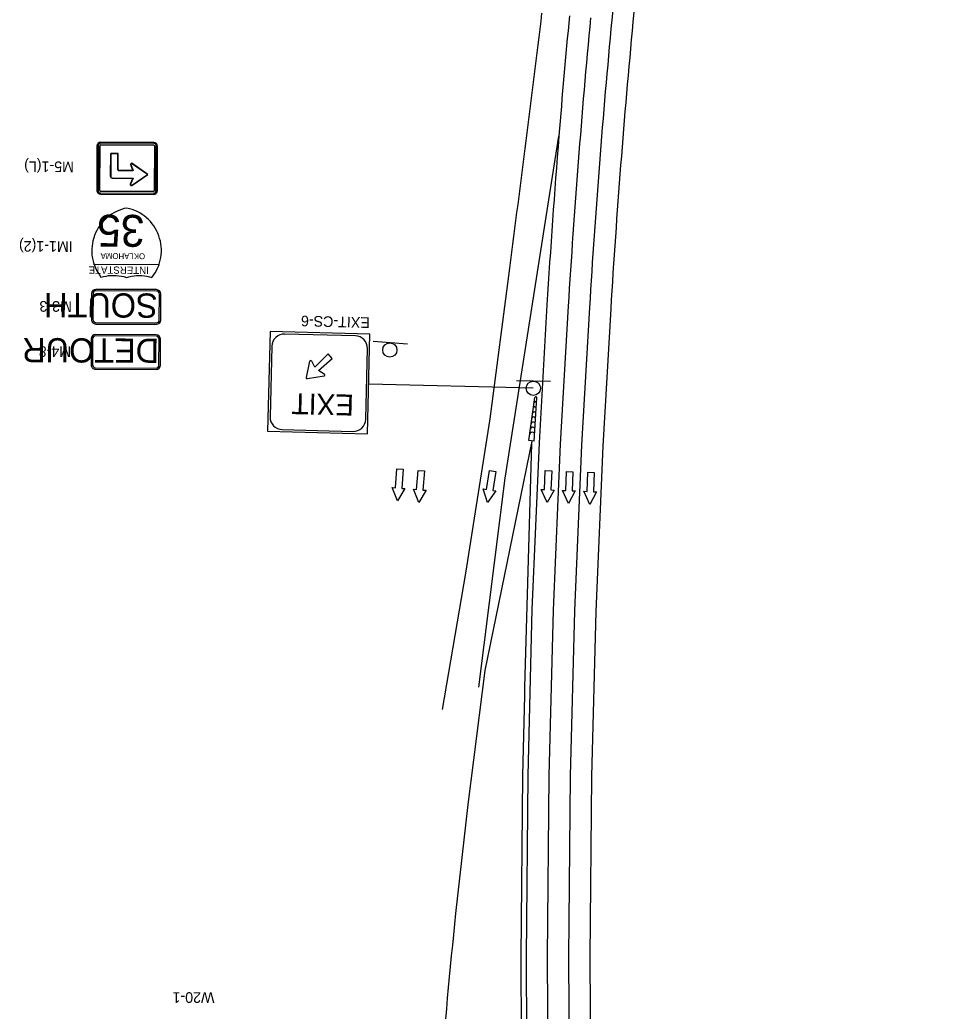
# Model space of a CAD drawing. Extents: x 2135767 to 2151731, y 141839 to 175894.
# Drawn here: x 2150479 to 2151007, y 146342 to 146901 of the extents above; entities that cross this region are included whole.
import ezdxf

# ---------------------------------------------------------------- set-up
doc = ezdxf.new("R2010")
doc.units = 0
for name, color, linetype in [('Default', 7, 'Continuous'), ('PR_Dimensions_Phase1', 7, 'Continuous'), ('PR_Phasing_Detour_1', 7, 'Continuous'), ('PR_Phasing_Traffic_Barrier_Phase_1', 7, 'Continuous'), ('PR_Phasing_Traffic_Control_Devices_1', 7, 'Continuous'), ('PR_Phasing_Traffic_Striping_Dashed_Phase_1', 7, 'Continuous'), ('PR_Phasing_Traffic_Striping_White_Phase_1', 7, 'Continuous'), ('PR_Phasing_Traffic_Striping_Yellow_Phase_1', 7, 'Continuous'), ('Pr_Traffic_Arrows_Phase_1', 7, 'Continuous'), ('PR_Traffic_Striping_Dashed', 7, 'Continuous'), ('PR_Txt_Phase_1', 7, 'Continuous')]:
    doc.layers.add(name, color=color, linetype=linetype)

# ---------------------------------------------------------------- blocks, each defined once
blk = doc.blocks.new('GRTATT')
at = {"layer": 'Default'}
for p, q in [((-0.09, 1.53), (-24.49, -0.82)), ((-0.03, 1.54), (0.03, -1.54)), ((0.09, -1.53), (-24.44, -1.81))]:
    blk.add_line(p, q, dxfattribs=at)
for centre, radius in [((-15.48, -0.83), 0.878), ((-12.48, -0.67), 1.01), ((-9.49, -0.51), 1.13), ((-6.49, -0.35), 1.26), ((-3.49, -0.19), 1.39), ((-24.46, -1.32), 0.496), ((-21.47, -1.16), 0.623), ((-18.47, -1), 0.751)]:
    blk.add_arc(centre, radius, 93.1763, 273.1763, dxfattribs=at)

msp = doc.modelspace()

# ---------------------------------------------------------------- linework, layer by layer
at = {"layer": 'PR_Dimensions_Phase1'}
msp.add_line((2150768.49, 146693.37), (2150675.68, 146695.77), dxfattribs=at)
at = {"layer": 'PR_Phasing_Detour_1'}
for p, q in [((2150554.54, 146831.98), (2150524.68, 146832.14)), ((2150522.51, 146829.99), (2150522.38, 146805.01)), ((2150523.12, 146829.98), (2150522.99, 146805.01)), ((2150523.12, 146829.98), (2150522.99, 146805.01)), ((2150524.13, 146829.98), (2150524, 146805)), ((2150524, 146805), (2150524.13, 146829.98)), ((2150554.53, 146830.36), (2150524.67, 146830.51)), ((2150524.67, 146830.51), (2150554.53, 146830.36)), ((2150554.54, 146831.37), (2150524.68, 146831.53)), ((2150554.54, 146831.37), (2150524.68, 146831.53)), ((2150554.94, 146804.84), (2150555.07, 146829.82)), ((2150555.07, 146829.82), (2150554.94, 146804.84)), ((2150555.95, 146804.84), (2150556.08, 146829.81)), ((2150555.95, 146804.84), (2150556.08, 146829.81)), ((2150556.56, 146804.83), (2150556.69, 146829.81)), ((2150530.35, 146825.63), (2150530.28, 146812.99)), ((2150534.51, 146825.61), (2150530.35, 146825.63)), ((2150534.46, 146816.78), (2150534.51, 146825.61)), ((2150542.93, 146816.04), (2150535.15, 146816.08)), ((2150541.56, 146819.52), (2150542.93, 146816.04)), ((2150551.24, 146813.92), (2150542.25, 146820.21)), ((2150531.32, 146811.94), (2150542.9, 146811.88)), ((2150542.9, 146811.88), (2150541.5, 146808.42)), ((2150542.19, 146807.72), (2150551.24, 146813.92)), ((2150524.54, 146804.46), (2150554.4, 146804.31)), ((2150554.4, 146804.31), (2150524.54, 146804.46)), ((2150524.53, 146803.45), (2150554.39, 146803.29)), ((2150524.53, 146803.45), (2150554.39, 146803.29)), ((2150524.53, 146802.84), (2150554.39, 146802.68)), ((2150557.76, 146762.87), (2150520.57, 146763.06)), ((2150556.13, 146748.95), (2150521.94, 146749.13)), ((2150556.12, 146748.14), (2150521.94, 146748.32)), ((2150519.48, 146746.7), (2150519.41, 146732.05)), ((2150520.3, 146746.7), (2150520.22, 146732.04)), ((2150557.67, 146731.85), (2150557.74, 146746.5)), ((2150558.48, 146731.84), (2150558.56, 146746.5)), ((2150521.84, 146730.41), (2150556.03, 146730.23)), ((2150521.84, 146729.59), (2150556.03, 146729.42)), ((2150519.28, 146721.24), (2150519.2, 146706.59)), ((2150520.09, 146721.24), (2150520.02, 146706.59)), ((2150555.92, 146723.5), (2150521.73, 146723.67)), ((2150555.92, 146722.68), (2150521.73, 146722.86)), ((2150557.46, 146706.39), (2150557.54, 146721.05)), ((2150558.27, 146706.39), (2150558.35, 146721.04)), ((2150687.92, 146718.92), (2150678.3, 146719.67)), ((2150697.54, 146718.18), (2150687.92, 146718.92)), ((2150521.63, 146704.14), (2150555.82, 146703.96)), ((2150521.64, 146704.95), (2150555.82, 146704.77))]:
    msp.add_line(p, q, dxfattribs=at)
for points in [[(2150534.24, 146816.69), (2150534.28, 146825.51), (2150530.12, 146825.54), (2150530.05, 146812.89)], [(2150541.33, 146819.43), (2150542.7, 146815.95), (2150534.93, 146815.99)], [(2150551.01, 146813.83), (2150542.02, 146820.12)], [(2150531.09, 146811.85), (2150542.68, 146811.79), (2150541.27, 146808.33)], [(2150541.96, 146807.63), (2150551.01, 146813.83)], [(2150553.5, 146755.82), (2150554.43, 146757.07), (2150555.28, 146758.37), (2150556.04, 146759.73), (2150556.72, 146761.13), (2150557.31, 146762.57), (2150557.8, 146764.05), (2150558.2, 146765.55), (2150558.5, 146767.08), (2150558.71, 146768.62), (2150558.81, 146770.18), (2150558.82, 146771.73), (2150558.73, 146773.29), (2150558.53, 146774.83), (2150558.24, 146776.36), (2150557.86, 146777.87), (2150557.37, 146779.35), (2150556.8, 146780.8), (2150556.13, 146782.21), (2150555.38, 146783.57), (2150554.54, 146784.88), (2150553.61, 146786.13), (2150552.61, 146787.33), (2150551.54, 146788.45), (2150550.4, 146789.51), (2150549.19, 146790.49), (2150547.92, 146791.39), (2150546.59, 146792.21), (2150545.22, 146792.95), (2150543.8, 146793.59), (2150542.35, 146794.14), (2150540.86, 146794.6), (2150539.35, 146794.97), (2150537.83, 146794.62), (2150536.34, 146794.18), (2150534.87, 146793.64), (2150533.45, 146793.01), (2150532.07, 146792.29), (2150530.74, 146791.48), (2150529.46, 146790.59), (2150528.24, 146789.63), (2150527.08, 146788.58), (2150526, 146787.46), (2150524.99, 146786.28), (2150524.05, 146785.04), (2150523.2, 146783.74), (2150522.43, 146782.38), (2150521.75, 146780.98), (2150521.16, 146779.54), (2150520.66, 146778.07), (2150520.26, 146776.56), (2150519.95, 146775.03), (2150519.74, 146773.49), (2150519.63, 146771.94), (2150519.62, 146770.38), (2150519.71, 146768.83), (2150519.9, 146767.28), (2150520.19, 146765.75), (2150520.57, 146764.24), (2150521.05, 146762.76), (2150521.62, 146761.31), (2150522.28, 146759.9), (2150523.03, 146758.54), (2150523.87, 146757.23), (2150524.79, 146755.97), (2150526.19, 146756.35), (2150527.62, 146756.64), (2150529.06, 146756.85), (2150530.51, 146756.97), (2150531.97, 146757.01), (2150533.43, 146756.96), (2150534.88, 146756.82), (2150536.32, 146756.6), (2150537.74, 146756.29), (2150539.14, 146755.89), (2150540.55, 146756.27), (2150541.98, 146756.57), (2150543.42, 146756.78), (2150544.87, 146756.9), (2150546.32, 146756.94), (2150547.78, 146756.88), (2150549.23, 146756.75), (2150550.67, 146756.52), (2150552.09, 146756.21), (2150553.5, 146755.82)]]:
    msp.add_lwpolyline(points, dxfattribs=at)
msp.add_circle((2150687.61, 146714.93), 4, dxfattribs=at)
for centre, radius, start, end in [((2150524.67, 146829.98), 2.16, 89.7019, 179.7019), ((2150554.53, 146829.82), 2.16, 359.7019, 89.7019), ((2150524.67, 146829.98), 1.55, 89.7019, 179.7019), ((2150524.67, 146829.98), 1.55, 89.7019, 179.7019), ((2150524.67, 146829.98), 0.537, 89.7019, 179.7019), ((2150524.67, 146829.98), 0.537, 89.7019, 179.7019), ((2150554.53, 146829.82), 0.537, 359.7019, 89.7019), ((2150554.53, 146829.82), 0.537, 359.7019, 89.7019), ((2150554.53, 146829.82), 1.55, 359.7019, 89.7019), ((2150554.53, 146829.82), 1.55, 359.7019, 89.7019), ((2150534.93, 146816.68), 0.694, 179.7019, 269.7019), ((2150535.16, 146816.78), 0.694, 179.7019, 269.7019), ((2150542.02, 146819.42), 0.694, 89.7019, 179.7019), ((2150542.25, 146819.51), 0.694, 89.7019, 179.7019), ((2150531.09, 146812.89), 1.04, 179.7019, 269.7019), ((2150531.32, 146812.98), 1.04, 179.7019, 269.7019), ((2150524.54, 146805), 2.16, 179.7019, 269.7019), ((2150524.54, 146805), 1.55, 179.7019, 269.7019), ((2150524.54, 146805), 1.55, 179.7019, 269.7019), ((2150524.54, 146805), 0.537, 179.7019, 269.7019), ((2150524.54, 146805), 0.537, 179.7019, 269.7019), ((2150541.96, 146808.32), 0.694, 179.7019, 269.7019), ((2150542.19, 146808.42), 0.694, 179.7019, 269.7019), ((2150554.4, 146804.84), 1.55, 269.7019, 359.7019), ((2150554.4, 146804.84), 1.55, 269.7019, 359.7019), ((2150554.4, 146804.84), 2.16, 269.7019, 359.7019), ((2150554.4, 146804.84), 0.537, 269.7019, 359.7019), ((2150554.4, 146804.84), 0.537, 269.7019, 359.7019), ((2150521.93, 146746.69), 2.44, 89.7019, 179.7019), ((2150521.93, 146746.69), 1.63, 89.7019, 179.7019), ((2150556.11, 146746.51), 1.63, 359.7019, 89.7019), ((2150556.11, 146746.51), 2.44, 359.7019, 89.7019), ((2150521.85, 146732.04), 2.44, 179.7019, 269.7019), ((2150521.85, 146732.04), 1.63, 179.7019, 269.7019), ((2150556.04, 146731.86), 1.63, 269.7019, 359.7019), ((2150556.04, 146731.86), 2.44, 269.7019, 359.7019), ((2150521.72, 146721.23), 2.44, 89.7019, 179.7019), ((2150521.72, 146721.23), 1.63, 89.7019, 179.7019), ((2150555.91, 146721.05), 2.44, 359.7019, 89.7019), ((2150555.91, 146721.05), 1.63, 359.7019, 89.7019), ((2150521.64, 146706.58), 2.44, 179.7019, 269.7019), ((2150521.64, 146706.58), 1.63, 179.7019, 269.7019), ((2150555.83, 146706.4), 2.44, 269.7019, 359.7019), ((2150555.83, 146706.4), 1.63, 269.7019, 359.7019)]:
    msp.add_arc(centre, radius, start, end, dxfattribs=at)
at = {"layer": 'PR_Phasing_Traffic_Barrier_Phase_1'}
for points in [[(2150767.73, 146663.55), (2150741.1, 146534.3), (2150731.5, 146458.73), (2150724.67, 146397.25)], [(2150767.45, 146662.17), (2150763.61, 146524.79), (2150763.49, 146520.33), (2150762.33, 146475.14), (2150761.37, 146372.8), (2150761.84, 146282.68), (2150762.58, 146173.1), (2150762.81, 146051.01), (2150763.85, 145920.4), (2150764.43, 145822.04), (2150764.95, 145730.37), (2150765.18, 145690.17)]]:
    msp.add_lwpolyline(points, dxfattribs=at)
msp.add_arc((2154239.46, 146028.83), 3534.05, 174.01627, 175.56826, dxfattribs=at)
at = {"layer": 'PR_Phasing_Traffic_Control_Devices_1'}
for p, q in [((2150620.18, 146725.33), (2150618.73, 146669.1)), ((2150676.41, 146723.88), (2150620.18, 146725.33)), ((2150674.96, 146667.65), (2150676.41, 146723.88)), ((2150652.86, 146712.76), (2150645.41, 146705.35)), ((2150647.39, 146703.33), (2150655.09, 146710.23)), ((2150655.09, 146710.23), (2150652.86, 146712.76)), ((2150642.4, 146708.64), (2150640.45, 146699.44)), ((2150645.41, 146705.35), (2150643.58, 146708.58)), ((2150650.64, 146701.27), (2150647.39, 146703.33)), ((2150641.21, 146698.83), (2150650.53, 146700.3)), ((2150768.59, 146697.37), (2150758.95, 146697.62)), ((2150778.24, 146697.12), (2150768.59, 146697.37)), ((2150618.73, 146669.1), (2150674.96, 146667.65))]:
    msp.add_line(p, q, dxfattribs=at)
for points in [[(2150668.18, 146722.92), (2150628.35, 146723.95)], [(2150621.14, 146717.1), (2150620.11, 146677.27)], [(2150674, 146675.88), (2150675.03, 146715.71)], [(2150652.86, 146712.76), (2150645.41, 146705.35), (2150643.58, 146708.58)], [(2150650.64, 146701.27), (2150647.39, 146703.33), (2150655.09, 146710.23), (2150652.86, 146712.76)], [(2150642.4, 146708.64), (2150640.45, 146699.44)], [(2150641.21, 146698.83), (2150650.53, 146700.3)], [(2150626.96, 146670.06), (2150666.79, 146669.03)]]:
    msp.add_lwpolyline(points, dxfattribs=at)
msp.add_circle((2150768.49, 146693.37), 4, dxfattribs=at)
for centre, radius, start, end in [((2150628.17, 146716.92), 7.03, 88.5212, 178.5212), ((2150668, 146715.89), 7.03, 358.5212, 88.5212), ((2150642.97, 146708.24), 0.699, 29.5789, 144.6011), ((2150642.97, 146708.24), 0.699, 29.5789, 144.6011), ((2150640.99, 146699.33), 0.543, 168.0494, 293.8906), ((2150640.99, 146699.33), 0.543, 168.0494, 293.8906), ((2150650.45, 146700.8), 0.507, 278.9476, 67.6995), ((2150650.45, 146700.8), 0.507, 278.9476, 67.6995), ((2150627.14, 146677.09), 7.03, 178.5212, 268.5212), ((2150666.97, 146676.06), 7.03, 268.5212, 358.5212)]:
    msp.add_arc(centre, radius, start, end, dxfattribs=at)
at = {"layer": 'PR_Phasing_Traffic_Striping_Dashed_Phase_1'}
for points in [[(2151007.42, 147966.34), (2150962.05, 147774.13), (2150952.59, 147736.16), (2150943.64, 147699.36), (2150930.36, 147641.44), (2150923.38, 147610.45), (2150917.1, 147581.15), (2150898.5, 147491.88), (2150876.21, 147370.91), (2150860.38, 147277.43), (2150847.06, 147191.86), (2150835.17, 147103.34), (2150823.22, 147005.9), (2150812.72, 146901.05)], [(2150788.16, 146739.66), (2150783.69, 146661.92), (2150779.71, 146568.33), (2150777.32, 146474.88), (2150776.37, 146372.77), (2150776.84, 146282.77), (2150777.58, 146173.16), (2150777.81, 146051.08), (2150778.85, 145920.51), (2150779.43, 145822.12), (2150779.95, 145730.45), (2150780.18, 145690.3)], [(2150800.14, 146738.93), (2150795.68, 146661.32), (2150791.7, 146567.92), (2150789.32, 146474.67), (2150788.37, 146372.74), (2150788.84, 146282.84), (2150789.58, 146173.21), (2150789.81, 146051.14), (2150790.85, 145920.59), (2150791.43, 145822.19), (2150791.95, 145730.52), (2150792.18, 145690.37)]]:
    msp.add_lwpolyline(points, dxfattribs=at)
for radius in [4837.59, 4825.59]:
    msp.add_arc((2155616.86, 146446.48), radius, 174.59467, 176.52543, dxfattribs=at)
at = {"layer": 'PR_Phasing_Traffic_Striping_White_Phase_1'}
for points in [[(2150737.86, 146524.84), (2150752.56, 146642.63), (2150782.89, 146835.51)], [(2150717.21, 146512.25), (2150730.41, 146589.21), (2150744.09, 146676.05), (2150755.22, 146761.02)], [(2150776.18, 146740.39), (2150771.71, 146662.52), (2150767.71, 146568.74), (2150765.33, 146475.09), (2150764.37, 146372.79), (2150764.84, 146282.7), (2150765.58, 146173.11), (2150765.81, 146051.02), (2150766.85, 145920.42), (2150767.43, 145822.06), (2150767.95, 145730.38), (2150768.18, 145690.22)]]:
    msp.add_lwpolyline(points, dxfattribs=at)
for centre, radius, start, end in [((2130411.85, 149402.07), 20514.09, 352.603044, 353.00792), ((2155616.86, 146446.48), 4849.59, 175.39884, 176.52543)]:
    msp.add_arc(centre, radius, start, end, dxfattribs=at)
at = {"layer": 'PR_Phasing_Traffic_Striping_Yellow_Phase_1'}
for points in [[(2150973.73, 147771.38), (2150971.08, 147760.75), (2150964.25, 147733.29), (2150955.32, 147696.6), (2150942.06, 147638.78), (2150935.1, 147607.87), (2150928.84, 147578.67), (2150910.27, 147489.57), (2150888.03, 147368.82), (2150872.23, 147275.51), (2150858.93, 147190.14), (2150847.07, 147101.81), (2150835.15, 147004.57), (2150824.67, 146899.92)], [(2150812.11, 146738.2), (2150807.66, 146660.73), (2150803.69, 146567.51), (2150801.32, 146474.47), (2150800.37, 146372.72), (2150800.84, 146282.91), (2150801.58, 146173.27), (2150801.81, 146051.2), (2150802.85, 145920.67), (2150803.43, 145822.26), (2150803.95, 145730.59), (2150804.18, 145690.43)]]:
    msp.add_lwpolyline(points, dxfattribs=at)
msp.add_arc((2155616.86, 146446.48), 4813.59, 174.59467, 176.52543, dxfattribs=at)
at = {"layer": 'Pr_Traffic_Arrows_Phase_1'}
for p, q in [((2150690.73, 146637.2), (2150691.57, 146647.97)), ((2150691.57, 146647.97), (2150695.16, 146647.69)), ((2150695.16, 146647.69), (2150694.32, 146636.93)), ((2150702.7, 146636.28), (2150703.53, 146647.04)), ((2150703.53, 146647.04), (2150707.12, 146646.76)), ((2150707.12, 146646.76), (2150706.29, 146636)), ((2150742.08, 146636.34), (2150743.76, 146647.01)), ((2150743.76, 146647.01), (2150747.32, 146646.45)), ((2150747.32, 146646.45), (2150745.64, 146635.78)), ((2150774.79, 146636.22), (2150775.25, 146647.01)), ((2150775.25, 146647.01), (2150778.85, 146646.85)), ((2150778.85, 146646.85), (2150778.39, 146636.06)), ((2150786.78, 146635.71), (2150787.24, 146646.5)), ((2150787.24, 146646.5), (2150790.84, 146646.34)), ((2150790.84, 146646.34), (2150790.38, 146635.55)), ((2150798.77, 146635.2), (2150799.23, 146645.99)), ((2150799.23, 146645.99), (2150802.83, 146645.83)), ((2150802.83, 146645.83), (2150802.37, 146635.04)), ((2150691.97, 146629.89), (2150688.94, 146637.34)), ((2150688.94, 146637.34), (2150690.73, 146637.2)), ((2150696.12, 146636.79), (2150691.97, 146629.89)), ((2150694.32, 146636.93), (2150696.12, 146636.79)), ((2150703.93, 146628.96), (2150700.9, 146636.42)), ((2150700.9, 146636.42), (2150702.7, 146636.28)), ((2150742.74, 146628.95), (2150740.31, 146636.62)), ((2150740.31, 146636.62), (2150742.08, 146636.34)), ((2150776.28, 146628.95), (2150772.99, 146636.29)), ((2150772.99, 146636.29), (2150774.79, 146636.22)), ((2150708.08, 146635.86), (2150703.93, 146628.96)), ((2150706.29, 146636), (2150708.08, 146635.86)), ((2150747.42, 146635.5), (2150742.74, 146628.95)), ((2150745.64, 146635.78), (2150747.42, 146635.5)), ((2150780.19, 146635.99), (2150776.28, 146628.95)), ((2150778.39, 146636.06), (2150780.19, 146635.99)), ((2150788.27, 146628.44), (2150784.98, 146635.78)), ((2150784.98, 146635.78), (2150786.78, 146635.71)), ((2150792.17, 146635.48), (2150788.27, 146628.44)), ((2150790.38, 146635.55), (2150792.17, 146635.48)), ((2150800.26, 146627.93), (2150796.97, 146635.27)), ((2150796.97, 146635.27), (2150798.77, 146635.2)), ((2150804.16, 146634.97), (2150800.26, 146627.93)), ((2150802.37, 146635.04), (2150804.16, 146634.97))]:
    msp.add_line(p, q, dxfattribs=at)
at = {"layer": 'PR_Traffic_Striping_Dashed'}
msp.add_arc((2155616.86, 146446.48), 4849.59, 174.59467, 175.39884, dxfattribs=at)

# ---------------------------------------------------------------- block references
at = {"layer": 'PR_Phasing_Traffic_Control_Devices_1', "rotation": -98.69831043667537}
msp.add_blockref('GRTATT', (2150767.49, 146663.74), dxfattribs=at)

# ---------------------------------------------------------------- texts
at = {"layer": 'PR_Phasing_Detour_1'}
for s, height, p in [('M5-1(L)', 6, (2150509.56, 146821.16)), ('35', 17.974, (2150549.37, 146791.07)), ('IM1-1(2)', 6, (2150508.87, 146776.23)), ('OKLAHOMA', 3.31, (2150549.67, 146769.44)), ('INTERSTATE', 4.084, (2150551.8, 146761.9)), ('M3-3', 6, (2150508.38, 146742.43)), ('SOUTH', 13.675, (2150556.75, 146746.78)), ('DETOUR', 13.675, (2150557.59, 146721.32)), ('M4-8', 6, (2150507.92, 146716.98))]:
    msp.add_text(s, height=height, rotation=179.7019, dxfattribs=at).set_placement(p)
at = {"layer": 'PR_Phasing_Traffic_Control_Devices_1'}
msp.add_text('EXIT', height=11.812, rotation=178.5212, dxfattribs=at).set_placement((2150667.52, 146689.73))
at = {"layer": 'PR_Txt_Phase_1'}
for s, rotation, p in [('EXIT-CS-6', 178.5212, (2150676.4, 146733.33)), ('W20-1', 179.9496, (2150588.75, 146352.92))]:
    msp.add_text(s, height=6, rotation=rotation, dxfattribs=at).set_placement(p)

doc.saveas('drawing.dxf')
